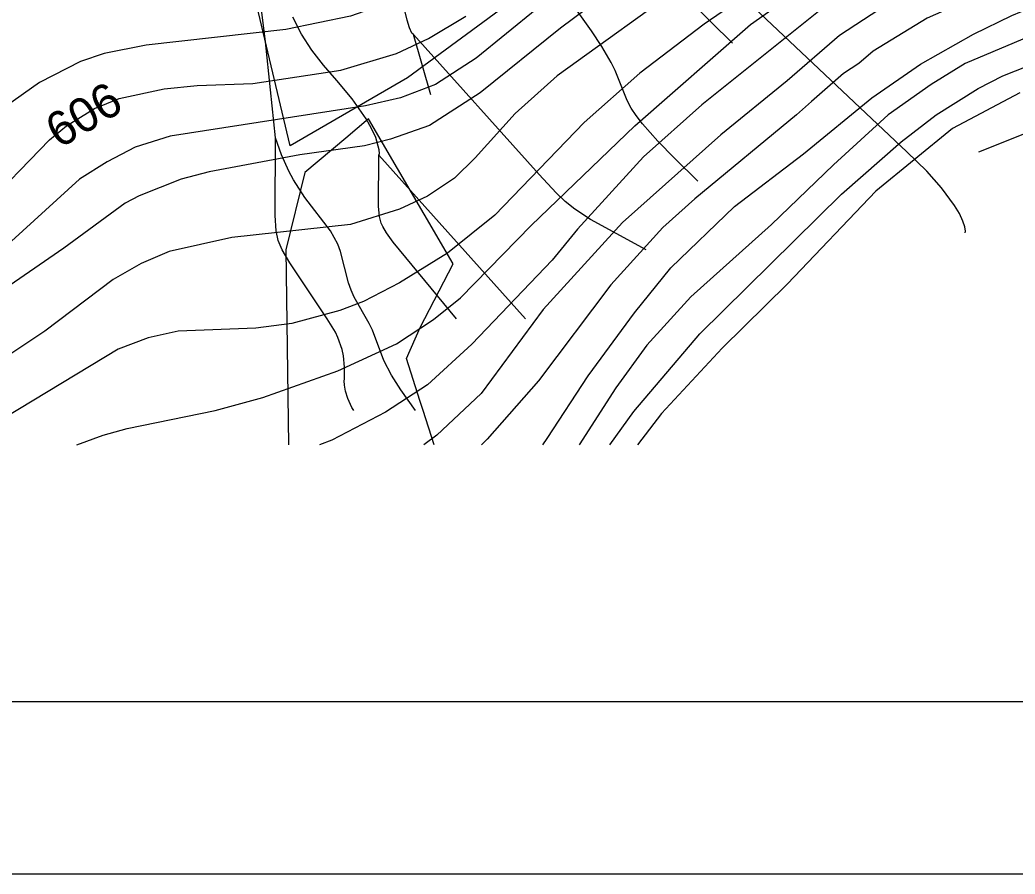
# Model space of a CAD drawing. Extents: x -709584 to -702006, y -1161789 to -1157496.
# Drawn here: x -708901.1 to -708612.5, y -1161765.5 to -1161517.8 of the extents above; entities that cross this region are included whole.
import ezdxf

# ---------------------------------------------------------------- set-up
doc = ezdxf.new("R2010")
doc.units = 0
for name, color, linetype in [('120_vrstevnice hlavní', 7, 'Continuous'), ('121_vrstevnice hlavní_popis', 7, 'Continuous'), ('122_vrstevnice základní', 7, 'Continuous'), ('408_BPEJ_linie', 7, 'Continuous'), ('411_akumulovaný odtok', 7, 'Continuous'), ('800_mřížka', 7, 'Continuous')]:
    doc.layers.add(name, color=color, linetype=linetype)

msp = doc.modelspace()

# ---------------------------------------------------------------- linework, layer by layer
at = {"layer": '120_vrstevnice hlavní'}
for points in [[(-708590.84, -1161483.13), (-708629.9, -1161500.78), (-708647.26, -1161511.62), (-708663.46, -1161522.33)], [(-708733.46, -1161512.06), (-708744.31, -1161520.16), (-708767.6, -1161538.96), (-708782.35, -1161548.36), (-708793.64, -1161552.41), (-708801.16, -1161554.29), (-708819.96, -1161556.9), (-708846.29, -1161561.81), (-708854.39, -1161563.99), (-708866.54, -1161568.76), (-708870.59, -1161570.93), (-708888.38, -1161583.95), (-708925.55, -1161609.55)], [(-708663.46, -1161522.33), (-708678.64, -1161535.49), (-708697.88, -1161551.11), (-708726.38, -1161576.57), (-708749.37, -1161601.74), (-708767.31, -1161626.18), (-708780.18, -1161638.19), (-708783.96, -1161641)], [(-708611.09, -1161538.96), (-708630.62, -1161549.23), (-708652.9, -1161567.46), (-708678.5, -1161594.36), (-708697.45, -1161613.02), (-708715.09, -1161631.97), (-708722.05, -1161641.01)]]:
    msp.add_lwpolyline(points, dxfattribs=at)
at = {"layer": '122_vrstevnice základní'}
for points in [[(-708678.79, -1161312.88), (-708658.68, -1161370.74), (-708656.95, -1161377.68), (-708655.79, -1161389.26), (-708655.93, -1161400.83), (-708657.53, -1161415), (-708659.26, -1161421.94), (-708662.73, -1161431.2), (-708667.94, -1161440.46), (-708676.62, -1161452.46), (-708686.74, -1161462.16), (-708716.97, -1161485.01), (-708751.25, -1161514.52), (-708768.76, -1161528.84), (-708780.62, -1161536.5), (-708790.74, -1161540.41), (-708800.87, -1161542.72), (-708857.57, -1161551.54), (-708867.69, -1161554.73), (-708875.79, -1161558.92), (-708883.89, -1161563.99), (-708903.57, -1161581.92)], [(-708884.64, -1161641), (-708876.95, -1161638.19), (-708870.01, -1161636.31), (-708844.55, -1161631.1), (-708830.66, -1161627.34), (-708808.97, -1161619.53), (-708791.9, -1161611.72), (-708781.2, -1161604.63), (-708773.39, -1161598.41), (-708752.84, -1161577.44), (-708722.76, -1161548.51), (-708689.2, -1161519.15), (-708652.32, -1161492.96), (-708639.59, -1161482.98), (-708613.99, -1161467.94), (-708601.11, -1161459.26), (-708590.99, -1161449.72), (-708586.21, -1161443.35), (-708584.05, -1161439.45), (-708581.88, -1161433.52), (-708580.86, -1161424.26), (-708581.73, -1161412.69)], [(-708527.78, -1161430.62), (-708530.38, -1161446.82), (-708532.55, -1161456.08), (-708537.33, -1161469.97), (-708542.97, -1161479.37), (-708546.44, -1161482.84), (-708550.78, -1161485.73), (-708558.44, -1161488.92), (-708576.67, -1161492.1), (-708596.48, -1161498.9), (-708638, -1161517.27), (-708653.62, -1161526.81), (-708657.81, -1161530.43), (-708662.3, -1161533.32), (-708671.56, -1161541.42), (-708675.89, -1161545.33), (-708705.4, -1161569.63), (-708714.66, -1161578.02), (-708729.7, -1161594.65), (-708750.68, -1161622.42), (-708765.57, -1161639.34), (-708767.3, -1161641.01)], [(-708608.18, -1161440.16), (-708612.71, -1161447.26), (-708616.16, -1161451.45), (-708621.07, -1161456.08), (-708667.36, -1161493.83), (-708684.57, -1161506.56), (-708702.65, -1161519), (-708721.31, -1161533.18), (-708737.51, -1161547.5), (-708763.41, -1161574.4), (-708777.15, -1161585.39), (-708791.03, -1161594.07), (-708801.45, -1161599.42), (-708808.39, -1161602.03), (-708822.28, -1161605.79), (-708832.69, -1161607.23), (-708855.25, -1161608.1), (-708863.93, -1161609.98), (-708872.61, -1161613.31), (-708905.45, -1161633.12), (-708925.53, -1161641)], [(-708607.91, -1161475.75), (-708638.87, -1161492.68), (-708646.53, -1161497.45), (-708665.19, -1161511.77), (-708703.38, -1161542.43), (-708720.3, -1161557.48), (-708739.39, -1161578.45), (-708746.77, -1161587.42), (-708770.06, -1161611.86), (-708782.93, -1161623.58), (-708795.08, -1161631.53), (-708810.7, -1161639.63), (-708814.23, -1161641)], [(-708707.14, -1161506.42), (-708745.32, -1161534.04), (-708757.47, -1161544.89), (-708769.05, -1161557.77), (-708775.12, -1161563.7), (-708782.93, -1161568.9), (-708791.03, -1161572.66), (-708805.21, -1161577.15), (-708839.63, -1161580.91), (-708857.86, -1161584.96), (-708865.96, -1161588.43), (-708874.06, -1161593.06), (-708893.87, -1161608.1), (-708907.9, -1161617.36)], [(-708624.55, -1161521.89), (-708613.41, -1161516.54), (-708596.63, -1161509.45)], [(-708792.02, -1161511.98), (-708805.21, -1161516.69), (-708824.01, -1161520.59), (-708864.51, -1161525.08), (-708876.66, -1161527.53), (-708883.6, -1161529.85), (-708895.46, -1161535.92), (-708905.45, -1161543.01), (-708913.69, -1161551.11), (-708932.06, -1161573.53), (-708938.28, -1161580.19), (-708948.12, -1161588.86), (-708955.06, -1161593.64), (-708962, -1161597.54), (-708977.62, -1161604.49), (-708996.72, -1161611.14), (-709012.34, -1161615.48), (-709036.64, -1161620.98), (-709044.45, -1161623.43), (-709060.36, -1161630.67), (-709078.6, -1161641)], [(-708912.68, -1161573.24), (-708892.57, -1161552.56), (-708887.65, -1161548.51), (-708879.55, -1161543.45), (-708872.32, -1161540.55), (-708859.3, -1161537.8), (-708849.76, -1161536.79), (-708833.56, -1161536.21), (-708808.1, -1161532.31), (-708791.9, -1161527.53), (-708782.64, -1161523.2), (-708771.79, -1161516.69)], [(-708749.49, -1161641.01), (-708748.22, -1161639.2), (-708736.36, -1161620.98), (-708722.9, -1161602.75), (-708712.34, -1161589.73), (-708693.83, -1161571.94), (-708673.87, -1161556.61), (-708654.05, -1161540.41), (-708639.88, -1161530.57), (-708624.55, -1161521.89)], [(-708604.73, -1161521.03), (-708627.01, -1161530.43), (-708636.84, -1161536.5), (-708649.28, -1161545.33), (-708665.19, -1161559.79), (-708683.13, -1161577.15), (-708706.56, -1161598.12), (-708719.29, -1161612.15), (-708728.26, -1161624.45), (-708738.89, -1161641.01)], [(-708616.01, -1161534.04), (-708601.84, -1161528.4)], [(-708729.99, -1161641.01), (-708723.05, -1161631.39), (-708703.96, -1161608.82), (-708662.88, -1161568.32), (-708645.52, -1161553.14), (-708635.39, -1161545.33), (-708623.24, -1161537.66), (-708616.01, -1161534.04)], [(-708622.96, -1161556.03), (-708606.76, -1161549.52)]]:
    msp.add_lwpolyline(points, dxfattribs=at)
at = {"layer": '408_BPEJ_linie'}
for points in [[(-708604.79, -1161444.56), (-708630.44, -1161437.29), (-708667.52, -1161427.27), (-708670.96, -1161426.82), (-708677.9, -1161457.99), (-708711.62, -1161479.44), (-708715.43, -1161481.91), (-708757.42, -1161511.46), (-708788.76, -1161534.58), (-708822.71, -1161554.32), (-708843.92, -1161465.04), (-708829.49, -1161460.04)], [(-708780.97, -1161641), (-708784.16, -1161631.08), (-708785.1, -1161628.15), (-708789, -1161616), (-708785, -1161607), (-708775.5, -1161588.5), (-708800, -1161546.5), (-708806.62, -1161552.05), (-708818.5, -1161562), (-708824, -1161584.5), (-708823.25, -1161641)]]:
    msp.add_lwpolyline(points, dxfattribs=at)
at = {"layer": '411_akumulovaný odtok'}
for p, q in [((-708781.99, -1161539.5), (-708786.99, -1161522)), ((-708754.49, -1161604.5), (-708796.99, -1161557))]:
    msp.add_line(p, q, dxfattribs=at)
for points in [[(-708826.99, -1161552), (-708829.91, -1161524.1), (-708830.97, -1161515.55), (-708832.14, -1161509.26), (-708832.68, -1161507.21), (-708834.08, -1161503.25), (-708837.57, -1161495.53), (-708843.27, -1161484.08), (-708848.15, -1161474.62), (-708851.32, -1161469.13), (-708854.02, -1161465.43), (-708857.63, -1161461.34), (-708866.99, -1161452)], [(-708704.49, -1161564.5), (-708711.32, -1161557.83), (-708716.06, -1161552.95), (-708720.53, -1161547.89), (-708722.37, -1161545.53), (-708723.8, -1161543.36), (-708724.99, -1161541.19), (-708728.45, -1161532.48), (-708729.6, -1161530.1), (-708732.33, -1161525.46), (-708735.37, -1161520.91), (-708740.22, -1161514.18), (-708753.69, -1161496.51), (-708759.06, -1161490.19), (-708764.71, -1161484.19), (-708791.99, -1161457)], [(-708694.49, -1161524.5), (-708713.1, -1161506.01), (-708714.94, -1161503.97), (-708715.97, -1161502.52), (-708716.65, -1161500.98), (-708717.06, -1161498.5), (-708717.15, -1161494.83), (-708716.99, -1161487)], [(-708626.99, -1161579.5), (-708626.88, -1161579.01), (-708627.07, -1161577.82), (-708627.62, -1161576.1), (-708628.63, -1161573.96), (-708630.06, -1161571.57), (-708633.83, -1161566.48), (-708638.08, -1161561.67), (-708643.84, -1161556.06), (-708716.99, -1161487)], [(-708786.99, -1161522), (-708787.48, -1161521.58), (-708788.16, -1161520.1), (-708788.85, -1161517.85), (-708791.25, -1161507.66)], [(-708796.99, -1161557), (-708796.84, -1161556.54), (-708796.93, -1161555.45), (-708797.94, -1161551.84), (-708799.13, -1161549.27), (-708800.73, -1161546.48), (-708804.79, -1161540.71), (-708809.19, -1161535.34), (-708813.04, -1161530.93), (-708816.48, -1161526.52), (-708819.42, -1161521.86), (-708821.94, -1161516.97)], [(-708719.49, -1161584.5), (-708735.61, -1161575.64), (-708740.19, -1161572.66), (-708743, -1161570.4), (-708745.6, -1161567.9), (-708750.55, -1161562.6), (-708786.99, -1161522)], [(-708806.99, -1161622), (-708806.99, -1161618.52), (-708807.33, -1161615.17), (-708807.68, -1161613.39), (-708808.89, -1161609.85), (-708809.63, -1161608.33), (-708812, -1161604.51), (-708822.89, -1161588.28), (-708825.09, -1161584.44), (-708826.19, -1161581.76), (-708826.79, -1161578.95), (-708827.13, -1161574.55), (-708826.99, -1161552)], [(-708786.37, -1161631.09), (-708790.7, -1161625.05), (-708793.37, -1161620.86), (-708795.58, -1161616.54), (-708798.83, -1161607.77), (-708799.8, -1161605.8), (-708804.15, -1161598.17), (-708805.06, -1161596.19), (-708805.83, -1161594.01), (-708808.16, -1161584.99), (-708808.95, -1161582.82), (-708811.06, -1161578.98), (-708818.45, -1161569.24), (-708821.74, -1161564.14), (-708823.09, -1161561.61), (-708825.25, -1161556.9), (-708826.99, -1161552)], [(-708774.49, -1161604.5), (-708792.86, -1161582.19), (-708794.82, -1161579.56), (-708795.91, -1161577.73), (-708796.33, -1161576.77), (-708796.82, -1161574.84), (-708797.11, -1161571.78), (-708796.99, -1161557)], [(-708804.3, -1161631.09), (-708804.85, -1161630.16), (-708805.98, -1161627.59), (-708806.66, -1161625.44), (-708807.01, -1161623.69), (-708807.11, -1161622.5), (-708806.99, -1161622)]]:
    msp.add_lwpolyline(points, dxfattribs=at)
at = {"layer": '800_mřížka'}
for points in [[(-702006.48, -1161765.53), (-709584.12, -1161765.53), (-709584.12, -1157496.46), (-702006.48, -1157496.46)], [(-702056.48, -1161715.53), (-709534.12, -1161715.53), (-709534.12, -1157546.46), (-702056.48, -1157546.46)]]:
    msp.add_lwpolyline(points, close=True, dxfattribs=at)

# ---------------------------------------------------------------- texts
at = {"layer": '121_vrstevnice hlavní_popis'}
msp.add_text('606', height=10, rotation=30.8914, dxfattribs=at).set_placement((-708889.7, -1161555.27))

doc.saveas('drawing.dxf')
